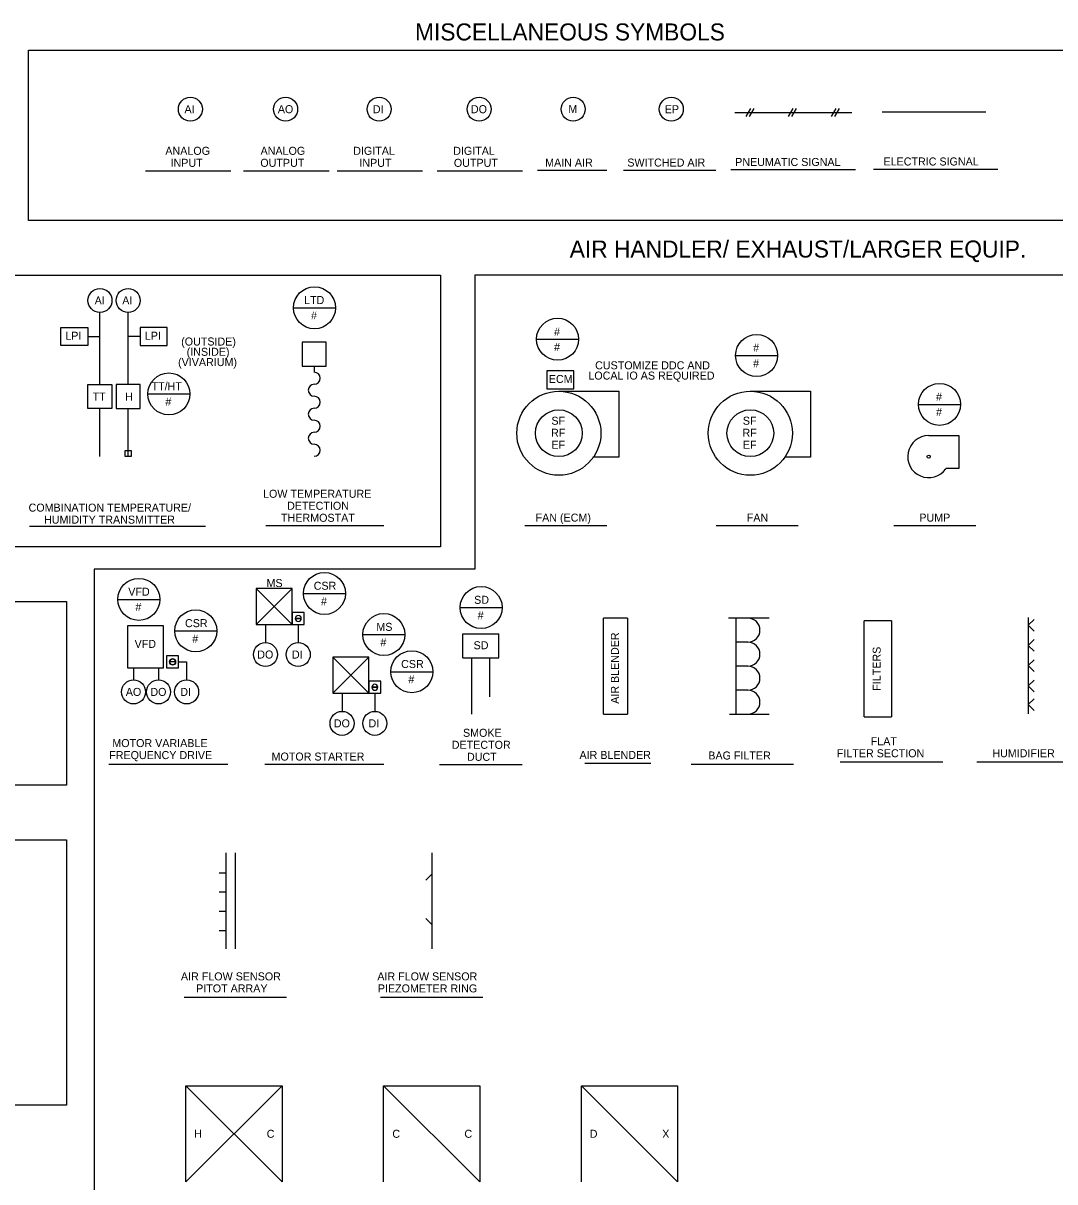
# Model space of a CAD drawing. Extents: x 10015 to 10283, y 10002 to 10184.
# Drawn here: x 10127.1 to 10212.9, y 10083.5 to 10180 of the extents above; entities that cross this region are included whole.
import ezdxf

# ---------------------------------------------------------------- set-up
doc = ezdxf.new("R2010")
doc.units = 0
for name, color, linetype in [('G-ANNO-TEXT', 7, 'Continuous'), ('G-DETL-LINE', 7, 'Continuous'), ('G-DETL-TEXT', 7, 'Continuous'), ('M-ANNO-NPLT', 7, 'Continuous')]:
    doc.layers.add(name, color=color, linetype=linetype)

msp = doc.modelspace()

# ---------------------------------------------------------------- linework, layer by layer
at = {"layer": 'G-ANNO-TEXT'}
for p, q in [((10137.239, 10167.7), (10144.357, 10167.7)), ((10145.403, 10167.7), (10152.521, 10167.7)), ((10153.19, 10167.7), (10160.308, 10167.7)), ((10161.512, 10167.7), (10168.63, 10167.7)), ((10169.884, 10167.757), (10175.638, 10167.757)), ((10177.034, 10167.757), (10184.713, 10167.757)), ((10185.976, 10167.806), (10196.344, 10167.806)), ((10197.835, 10167.848), (10208.204, 10167.848)), ((10127.598, 10138.112), (10142.249, 10138.112)), ((10147.258, 10138.166), (10157.082, 10138.166)), ((10168.821, 10138.166), (10175.647, 10138.166)), ((10184.758, 10138.166), (10191.584, 10138.166)), ((10199.528, 10138.166), (10206.355, 10138.166)), ((10134.197, 10118.291), (10144.107, 10118.291)), ((10147.171, 10118.291), (10157.08, 10118.291)), ((10161.706, 10118.275), (10168.59, 10118.275)), ((10173.803, 10118.385), (10179.308, 10118.385)), ((10182.652, 10118.291), (10191.182, 10118.291)), ((10195.078, 10118.477), (10203.608, 10118.477)), ((10206.448, 10118.477), (10214.978, 10118.477)), ((10140.454, 10098.897), (10148.985, 10098.897)), ((10156.804, 10098.897), (10165.334, 10098.897))]:
    msp.add_line(p, q, dxfattribs=at)
at = {"layer": 'G-DETL-LINE'}
for p, q in [((10187.239, 10172.233), (10187.624, 10172.9)), ((10187.527, 10172.233), (10187.912, 10172.9)), ((10190.763, 10172.233), (10191.148, 10172.9)), ((10191.052, 10172.233), (10191.437, 10172.9)), ((10194.339, 10172.233), (10194.724, 10172.9)), ((10194.628, 10172.233), (10195.013, 10172.9)), ((10186.292, 10172.566), (10196.045, 10172.566)), ((10198.572, 10172.608), (10207.194, 10172.608)), ((10133.456, 10149.91), (10133.456, 10155.91)), ((10135.798, 10149.91), (10135.798, 10155.91)), ((10130.206, 10154.66), (10132.456, 10154.66)), ((10130.206, 10153.16), (10130.206, 10154.66)), ((10132.456, 10154.66), (10132.456, 10153.16)), ((10139.048, 10154.66), (10136.798, 10154.66)), ((10136.798, 10154.66), (10136.798, 10153.16)), ((10139.048, 10153.16), (10139.048, 10154.66)), ((10132.456, 10153.91), (10133.456, 10153.91)), ((10136.798, 10153.91), (10135.798, 10153.91)), ((10132.456, 10153.16), (10130.206, 10153.16)), ((10136.798, 10153.16), (10139.048, 10153.16)), ((10150.294, 10153.434), (10150.294, 10151.434)), ((10152.294, 10153.434), (10150.294, 10153.434)), ((10152.294, 10151.434), (10152.294, 10153.434)), ((10150.294, 10151.434), (10152.277, 10151.434)), ((10151.294, 10151.434), (10151.294, 10150.934)), ((10172.898, 10151.058), (10170.648, 10151.058)), ((10170.648, 10151.058), (10170.648, 10149.558)), ((10172.898, 10149.558), (10172.898, 10151.058)), ((10132.456, 10149.91), (10134.456, 10149.91)), ((10132.456, 10147.91), (10132.456, 10149.91)), ((10134.456, 10149.91), (10134.456, 10147.91)), ((10134.798, 10149.91), (10134.798, 10147.91)), ((10136.798, 10149.91), (10134.798, 10149.91)), ((10136.798, 10147.91), (10136.798, 10149.91)), ((10170.648, 10149.558), (10172.898, 10149.558)), ((10171.651, 10149.355), (10176.651, 10149.355)), ((10176.651, 10149.355), (10176.651, 10143.855)), ((10187.589, 10149.355), (10192.589, 10149.355)), ((10192.589, 10149.355), (10192.589, 10143.855)), ((10134.456, 10147.91), (10132.456, 10147.91)), ((10133.456, 10143.91), (10133.456, 10147.91)), ((10134.798, 10147.91), (10136.798, 10147.91)), ((10135.798, 10143.91), (10135.798, 10147.91)), ((10202.437, 10145.652), (10204.937, 10145.652)), ((10204.937, 10145.652), (10204.937, 10142.902)), ((10176.651, 10143.855), (10174.494, 10143.855)), ((10192.589, 10143.855), (10190.431, 10143.855)), ((10204.937, 10142.902), (10203.859, 10142.902)), ((10146.459, 10132.924), (10146.459, 10129.924)), ((10149.459, 10132.924), (10146.459, 10132.924)), ((10146.459, 10132.924), (10149.459, 10129.924)), ((10149.459, 10132.924), (10146.459, 10129.924)), ((10149.459, 10129.924), (10149.459, 10132.924)), ((10150.459, 10130.924), (10149.459, 10130.924)), ((10149.459, 10130.924), (10149.459, 10129.924)), ((10149.959, 10130.424), (10149.709, 10130.424)), ((10149.709, 10130.424), (10149.959, 10130.424)), ((10150.209, 10130.424), (10149.959, 10130.424)), ((10149.959, 10130.424), (10150.209, 10130.424)), ((10150.459, 10129.924), (10150.459, 10130.924)), ((10175.365, 10122.453), (10175.365, 10130.453)), ((10177.365, 10130.453), (10175.365, 10130.453)), ((10177.365, 10130.453), (10177.365, 10122.453)), ((10189.169, 10130.453), (10185.774, 10130.453)), ((10186.392, 10130.453), (10186.392, 10122.453)), ((10210.713, 10130.496), (10210.713, 10122.496)), ((10210.713, 10129.858), (10211.205, 10130.349)), ((10138.748, 10129.81), (10135.748, 10129.81)), ((10135.748, 10129.81), (10135.748, 10126.31)), ((10138.748, 10126.31), (10138.748, 10129.81)), ((10146.459, 10129.924), (10149.459, 10129.924)), ((10147.232, 10129.924), (10147.232, 10128.424)), ((10149.459, 10129.924), (10150.459, 10129.924)), ((10149.959, 10129.924), (10149.959, 10128.424)), ((10199.343, 10130.224), (10197.069, 10130.224)), ((10197.069, 10122.224), (10197.069, 10130.224)), ((10199.343, 10130.224), (10199.343, 10122.224)), ((10210.713, 10129.858), (10211.205, 10129.367)), ((10163.648, 10127.154), (10163.648, 10129.154)), ((10163.648, 10129.154), (10166.648, 10129.154)), ((10166.648, 10127.154), (10166.648, 10129.154)), ((10187.392, 10128.453), (10186.392, 10128.453)), ((10210.713, 10128.181), (10211.205, 10128.672)), ((10210.713, 10128.181), (10211.205, 10127.69)), ((10139.006, 10127.31), (10139.006, 10126.31)), ((10140.006, 10127.31), (10139.006, 10127.31)), ((10139.506, 10126.81), (10139.256, 10126.81)), ((10139.756, 10126.81), (10139.506, 10126.81)), ((10140.006, 10126.31), (10140.006, 10127.31)), ((10140.006, 10126.81), (10140.671, 10126.81)), ((10140.671, 10126.81), (10140.671, 10125.31)), ((10152.832, 10127.192), (10152.832, 10124.192)), ((10155.832, 10127.192), (10152.832, 10127.192)), ((10152.832, 10127.192), (10155.832, 10124.192)), ((10155.832, 10127.192), (10152.832, 10124.192)), ((10155.832, 10124.192), (10155.832, 10127.192)), ((10163.648, 10127.154), (10166.648, 10127.154)), ((10164.398, 10122.453), (10164.398, 10127.154)), ((10165.898, 10123.904), (10165.898, 10127.154)), ((10210.713, 10126.496), (10211.205, 10126.988)), ((10210.713, 10126.496), (10211.205, 10126.005)), ((10135.748, 10126.31), (10138.748, 10126.31)), ((10136.248, 10126.31), (10136.248, 10125.31)), ((10138.329, 10126.31), (10138.329, 10125.31)), ((10139.006, 10126.31), (10140.006, 10126.31)), ((10187.392, 10126.453), (10186.392, 10126.453)), ((10156.832, 10125.192), (10155.832, 10125.192)), ((10155.832, 10125.192), (10155.832, 10124.192)), ((10156.332, 10124.692), (10156.082, 10124.692)), ((10156.082, 10124.692), (10156.332, 10124.692)), ((10156.582, 10124.692), (10156.332, 10124.692)), ((10156.332, 10124.692), (10156.582, 10124.692)), ((10156.832, 10124.192), (10156.832, 10125.192)), ((10210.713, 10124.804), (10211.205, 10125.295)), ((10210.713, 10124.804), (10211.205, 10124.312)), ((10152.832, 10124.192), (10155.832, 10124.192)), ((10153.605, 10124.192), (10153.605, 10122.692)), ((10155.832, 10124.192), (10156.832, 10124.192)), ((10156.332, 10124.192), (10156.332, 10122.692)), ((10187.392, 10124.453), (10186.392, 10124.453)), ((10210.713, 10123.248), (10211.205, 10123.74)), ((10210.713, 10123.248), (10211.205, 10122.757)), ((10175.365, 10122.453), (10177.365, 10122.453)), ((10185.861, 10122.453), (10189.169, 10122.453)), ((10197.069, 10122.224), (10199.343, 10122.224)), ((10143.935, 10110.916), (10143.935, 10102.916)), ((10144.72, 10110.916), (10144.72, 10102.916)), ((10161.069, 10110.916), (10161.069, 10102.916)), ((10143.935, 10109.227), (10143.376, 10109.227)), ((10160.578, 10108.639), (10161.069, 10109.131)), ((10143.935, 10107.643), (10143.376, 10107.643)), ((10143.935, 10106.027), (10143.376, 10106.027)), ((10160.578, 10105.441), (10161.069, 10104.95)), ((10143.935, 10104.411), (10143.376, 10104.411)), ((10140.612, 10091.512), (10148.612, 10091.512)), ((10148.612, 10091.512), (10140.612, 10083.512)), ((10140.612, 10091.512), (10148.612, 10083.512)), ((10140.612, 10083.512), (10140.612, 10091.512)), ((10148.612, 10091.512), (10148.612, 10083.512)), ((10157.069, 10091.512), (10165.069, 10091.512)), ((10157.069, 10083.512), (10157.069, 10091.512)), ((10157.069, 10091.512), (10165.069, 10083.512)), ((10165.069, 10091.512), (10165.069, 10083.512)), ((10173.527, 10091.512), (10181.527, 10091.512)), ((10173.527, 10083.512), (10173.527, 10091.512)), ((10173.527, 10091.512), (10181.527, 10083.512)), ((10181.527, 10091.512), (10181.527, 10083.512))]:
    msp.add_line(p, q, dxfattribs=at)
for points in [[(10127.501, 10177.757), (10218.361, 10177.757), (10218.361, 10163.559), (10127.501, 10163.559)], [(10015.495, 10159.007), (10161.797, 10159.007), (10161.797, 10136.385), (10015.495, 10136.385)], [(10136.048, 10144.41), (10136.048, 10143.91), (10135.548, 10143.91), (10135.548, 10144.41)], [(10015.495, 10131.834), (10130.67, 10131.834), (10130.67, 10116.546), (10015.495, 10116.546)], [(10015.495, 10111.994), (10130.67, 10111.994), (10130.67, 10089.891), (10015.495, 10089.891)]]:
    msp.add_lwpolyline(points, close=True, dxfattribs=at)
msp.add_lwpolyline([(10164.661, 10159.007), (10164.661, 10134.537), (10132.976, 10134.537), (10132.976, 10061.022), (10218.412, 10061.022), (10218.412, 10159.007), (10164.661, 10159.007)], dxfattribs=at)
for centre, radius in [((10140.98, 10172.837), 1), ((10148.908, 10172.837), 1), ((10156.695, 10172.837), 1), ((10165.017, 10172.837), 1), ((10172.849, 10172.837), 1), ((10181.012, 10172.837), 1), ((10133.456, 10156.91), 1), ((10135.798, 10156.91), 1), ((10171.651, 10145.855), 3.5), ((10187.589, 10145.855), 3.5), ((10171.651, 10145.855), 1.944), ((10187.589, 10145.855), 1.944), ((10202.437, 10143.902), 0.127), ((10147.232, 10127.424), 1), ((10149.959, 10127.424), 1), ((10139.506, 10126.81), 0.25), ((10136.248, 10124.31), 1), ((10138.329, 10124.31), 1), ((10140.671, 10124.31), 1), ((10153.605, 10121.692), 1), ((10156.332, 10121.692), 1)]:
    msp.add_circle(centre, radius, dxfattribs=at)
for centre, radius, start, end in [((10151.294, 10150.434), 0.5, 270, 90), ((10151.294, 10149.434), 0.5, 90, 270), ((10151.294, 10148.434), 0.5, 270, 90), ((10151.294, 10147.434), 0.5, 90, 270), ((10151.294, 10146.434), 0.5, 270, 90), ((10151.294, 10145.434), 0.5, 90, 270), ((10151.294, 10144.434), 0.5, 270, 90), ((10202.437, 10143.902), 1.75, 90.70662, 324.91907), ((10149.959, 10130.424), 0.25, 0, 180), ((10149.959, 10130.424), 0.25, 180, 0), ((10187.392, 10129.453), 1, 270, 90), ((10187.392, 10127.453), 1, 270, 90), ((10139.506, 10126.81), 0.25, 0, 180), ((10139.506, 10126.81), 0.25, 180, 0), ((10187.392, 10125.453), 1, 270, 90), ((10156.332, 10124.692), 0.25, 0, 180), ((10156.332, 10124.692), 0.25, 180, 0), ((10187.392, 10123.453), 1, 270, 90)]:
    msp.add_arc(centre, radius, start, end, dxfattribs=at)
at = {"layer": 'G-DETL-TEXT'}
for centre in [(10151.313, 10156.3), (10171.546, 10153.682), (10188.114, 10152.325), (10139.192, 10149.125), (10203.338, 10148.253), (10152.14, 10132.508), (10136.692, 10132.014), (10165.183, 10131.337), (10141.429, 10129.395), (10157.088, 10129.086), (10159.417, 10125.993)]:
    msp.add_circle(centre, 1.75, dxfattribs=at)
at = {"layer": 'M-ANNO-NPLT'}
for p, q in [((10149.563, 10156.3), (10153.063, 10156.3)), ((10169.796, 10153.682), (10173.296, 10153.682)), ((10186.364, 10152.325), (10189.864, 10152.325)), ((10137.442, 10149.125), (10140.942, 10149.125)), ((10201.588, 10148.253), (10205.088, 10148.253)), ((10150.39, 10132.508), (10153.89, 10132.508)), ((10134.942, 10132.014), (10138.442, 10132.014)), ((10163.433, 10131.337), (10166.933, 10131.337)), ((10139.679, 10129.395), (10143.179, 10129.395)), ((10155.338, 10129.086), (10158.838, 10129.086)), ((10157.667, 10125.993), (10161.167, 10125.993))]:
    msp.add_line(p, q, dxfattribs=at)

# ---------------------------------------------------------------- texts
at = {"layer": 'G-ANNO-TEXT'}
for s, height, p in [('MISCELLANEOUS SYMBOLS', 1.41667, (10159.68, 10178.562)), ('ANALOG ', 0.6667, (10138.897, 10169.037)), ('ANALOG ', 0.6667, (10146.825, 10169.037)), ('DIGITAL', 0.6667, (10154.534, 10169.037)), ('DIGITAL', 0.6667, (10162.857, 10169.037)), ('INPUT', 0.6667, (10139.333, 10168.037)), ('OUTPUT', 0.6667, (10146.803, 10168.037)), ('INPUT', 0.6667, (10155.048, 10168.037)), ('OUTPUT', 0.6667, (10162.913, 10168.037)), ('MAIN AIR', 0.6667, (10170.509, 10168.059)), ('SWITCHED AIR', 0.66667, (10177.351, 10168.059)), ('PNEUMATIC SIGNAL', 0.66667, (10186.33, 10168.108)), ('ELECTRIC SIGNAL', 0.66667, (10198.675, 10168.149)), ('AIR HANDLER/ EXHAUST/LARGER EQUIP.', 1.41667, (10172.556, 10160.484)), ('LOW TEMPERATURE', 0.66667, (10147.031, 10140.478)), ('COMBINATION TEMPERATURE/', 0.66667, (10127.513, 10139.324)), ('DETECTION', 0.6667, (10149.029, 10139.478)), ('THERMOSTAT', 0.6667, (10148.529, 10138.478)), ('FAN (ECM)', 0.6667, (10169.717, 10138.492)), ('FAN', 0.6667, (10187.294, 10138.492)), ('PUMP', 0.6667, (10201.658, 10138.492)), ('HUMIDITY TRANSMITTER', 0.66667, (10128.799, 10138.324)), ('MS', 0.6667, (10147.32, 10133.043)), ('SMOKE', 0.6667, (10163.672, 10120.572)), ('MOTOR VARIABLE', 0.66667, (10134.484, 10119.716)), ('DETECTOR', 0.6667, (10162.74, 10119.572)), ('FLAT', 0.6667, (10197.61, 10119.868)), ('FREQUENCY DRIVE', 0.66667, (10134.225, 10118.716)), ('MOTOR STARTER', 0.66667, (10147.738, 10118.593)), ('DUCT', 0.6667, (10164.004, 10118.572)), ('AIR BLENDER', 0.66667, (10173.37, 10118.726)), ('BAG FILTER', 0.6667, (10184.093, 10118.682)), ('FILTER SECTION', 0.66667, (10194.79, 10118.868)), ('HUMIDIFIER', 0.6667, (10207.732, 10118.868)), ('AIR FLOW SENSOR', 0.66667, (10140.194, 10100.287)), ('AIR FLOW SENSOR', 0.66667, (10156.544, 10100.287)), ('PITOT ARRAY', 0.66667, (10141.459, 10099.287)), ('PIEZOMETER RING', 0.66667, (10156.585, 10099.287))]:
    msp.add_text(s, height=height, dxfattribs=at).set_placement(p)
at = {"layer": 'G-DETL-LINE'}
for s, height, p in [('AI', 0.6667, (10140.49, 10172.503)), ('AO', 0.6667, (10148.258, 10172.503)), ('DI', 0.6667, (10156.169, 10172.503)), ('DO', 0.6667, (10164.332, 10172.504)), ('M', 0.667, (10172.439, 10172.525)), ('EP', 0.6667, (10180.469, 10172.504)), ('AI', 0.6667, (10133.015, 10156.577)), ('AI', 0.6667, (10135.311, 10156.577)), ('LPI', 0.6667, (10130.572, 10153.639)), ('LPI', 0.6667, (10137.187, 10153.639)), ('(OUTSIDE)', 0.6667, (10140.215, 10153.156)), ('(INSIDE)', 0.6667, (10140.672, 10152.3)), ('(VIVARIUM)', 0.6667, (10139.958, 10151.443)), ('CUSTOMIZE DDC AND', 0.66667, (10174.672, 10151.175)), ('ECM', 0.6667, (10170.815, 10150.037)), ('LOCAL IO AS REQUIRED', 0.66667, (10174.108, 10150.319)), ('TT', 0.6667, (10132.845, 10148.576)), ('H', 0.667, (10135.557, 10148.576)), ('VFD', 0.6667, (10136.339, 10127.977)), ('SD', 0.6667, (10164.555, 10127.862)), ('DO', 0.6667, (10146.549, 10127.09)), ('DI', 0.6667, (10149.436, 10127.09)), ('AO', 0.6667, (10135.605, 10123.977)), ('DO', 0.6667, (10137.65, 10123.977)), ('DI', 0.6667, (10140.144, 10123.977)), ('DO', 0.6667, (10152.922, 10121.359)), ('DI', 0.6667, (10155.808, 10121.359)), ('H', 0.667, (10141.302, 10087.179)), ('C', 0.667, (10147.337, 10087.179)), ('C', 0.667, (10157.794, 10087.179)), ('C', 0.667, (10163.794, 10087.179)), ('D', 0.667, (10174.222, 10087.179)), ('X', 0.667, (10180.255, 10087.179))]:
    msp.add_text(s, height=height, dxfattribs=at).set_placement(p)
for s, height, p in [('AIR BLENDER', 0.66667, (10176.65, 10123.322)), ('FILTERS', 0.6667, (10198.44, 10124.41))]:
    msp.add_text(s, height=height, rotation=90, dxfattribs=at).set_placement(p)
at = {"layer": 'G-DETL-TEXT'}
for s, height, p in [('LTD', 0.6667, (10150.449, 10156.609)), ('#', 0.667, (10151.023, 10155.325)), ('#', 0.667, (10171.256, 10153.99)), ('#', 0.667, (10171.256, 10152.706)), ('#', 0.667, (10187.824, 10152.634)), ('#', 0.667, (10187.824, 10151.349)), ('TT/HT', 0.6667, (10137.749, 10149.434)), ('#', 0.667, (10138.902, 10148.15)), ('#', 0.667, (10203.048, 10148.562)), ('#', 0.667, (10203.048, 10147.278)), ('CSR', 0.6667, (10151.247, 10132.817)), ('VFD', 0.6667, (10135.811, 10132.323)), ('SD', 0.6667, (10164.602, 10131.646)), ('#', 0.667, (10136.402, 10131.038)), ('#', 0.667, (10151.85, 10131.533)), ('CSR', 0.6667, (10140.535, 10129.703)), ('#', 0.667, (10164.893, 10130.362)), ('MS', 0.6667, (10156.461, 10129.395)), ('#', 0.667, (10141.139, 10128.419)), ('#', 0.667, (10156.798, 10128.111)), ('CSR', 0.6667, (10158.523, 10126.302)), ('#', 0.667, (10159.127, 10125.018))]:
    msp.add_text(s, height=height, dxfattribs=at).set_placement(p)
at = {"layer": 'M-ANNO-NPLT'}
for s, p in [('SF', (10171.032, 10146.559)), ('SF', (10186.969, 10146.559)), ('RF', (10171.003, 10145.559)), ('RF', (10186.94, 10145.559)), ('EF', (10171.03, 10144.559)), ('EF', (10186.967, 10144.559))]:
    msp.add_text(s, height=0.6667, dxfattribs=at).set_placement(p)

doc.saveas('drawing.dxf')
